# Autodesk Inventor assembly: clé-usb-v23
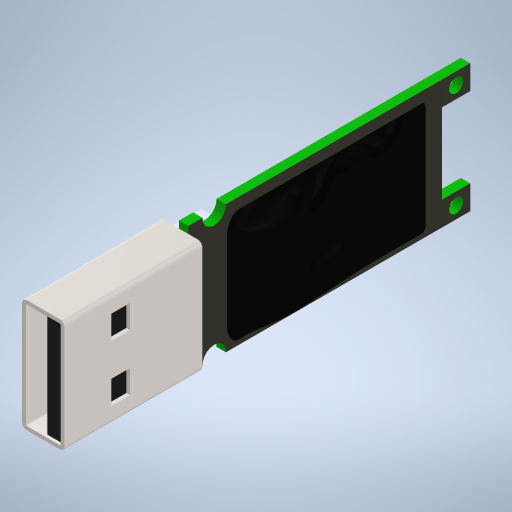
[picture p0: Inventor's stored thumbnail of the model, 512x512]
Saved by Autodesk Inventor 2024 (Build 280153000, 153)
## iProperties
Created: 2024-10
Part Number: clé-usb-v23
Document SubType Name: Assembly
Designer: bruno
Author: bruno
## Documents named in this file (4)
- C:\Users\bruno\Documents\1-Cours-2024-25\1STI2D\IT\Clé-USB\Cle-USB\clé-usb-v23.iam
- C:\Users\bruno\Documents\1-Cours-2024-25\1STI2D\IT\Clé-USB\Cle-USB\plaque-1.ipt
- C:\Users\bruno\Documents\1-Cours-2024-25\1STI2D\IT\Clé-USB\Cle-USB\blindage.ipt
- C:\Users\bruno\Documents\1-Cours-2024-25\1STI2D\IT\Clé-USB\Cle-USB\connecteur.ipt
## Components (3 placed, 3 different names)
1. plaque-1:1 — Placage:3, Placage:4, Affleurement:2
2. blindage:1 — Placage:1, Affleurement:1, Placage:2, Placage:4, Affleurement:2
3. connecteur:1 — Placage:1, Affleurement:1, Placage:2, Placage:3
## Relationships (6: Mate 4, Flush 2)
- Placage:1 [Mate]: blindage:1 ↔ connecteur:1
- Affleurement:1 [Flush]: blindage:1 ↔ connecteur:1
- Placage:2 [Mate]: blindage:1 ↔ connecteur:1
- Placage:3 [Mate]: plaque-1:1 ↔ connecteur:1
- Placage:4 [Mate]: plaque-1:1 ↔ blindage:1
- Affleurement:2 [Flush]: plaque-1:1 ↔ blindage:1
